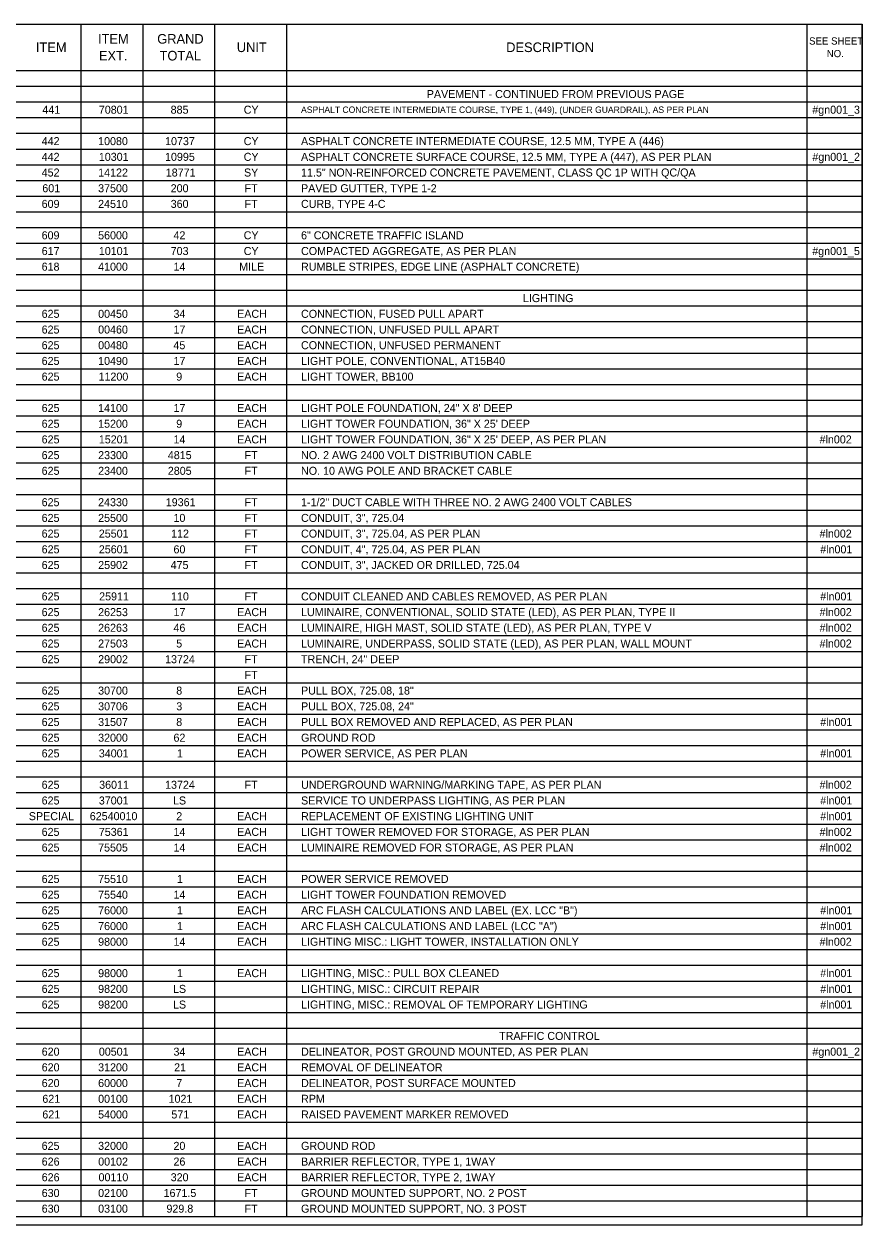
# Model space of a CAD drawing. Extents: x -542 to 295, y -281 to 32.
# Drawn here: x -400.58 to -385.9, y -100.59 to -79.59 of the extents above; entities that cross this region are included whole.
import ezdxf

# ---------------------------------------------------------------- set-up
doc = ezdxf.new("R2010")
doc.units = 0
for name, color, linetype in [('SC_Scratch1', 7, 'Continuous'), ('SH_Data', 7, 'Continuous'), ('SH_Text', 7, 'Continuous')]:
    doc.layers.add(name, color=color, linetype=linetype)

msp = doc.modelspace()

# ---------------------------------------------------------------- linework, layer by layer
at = {"layer": 'SC_Scratch1'}
msp.add_lwpolyline([(-416.421, -79.593), (-385.921, -79.593), (-385.921, -100.593), (-416.421, -100.593)], close=True, dxfattribs=at)
at = {"layer": 'SH_Data'}
for p, q in [((-416.419, -79.593), (-385.919, -79.593)), ((-399.583, -79.593), (-399.583, -100.444)), ((-398.498, -79.593), (-398.498, -100.444)), ((-397.242, -79.593), (-397.242, -100.444)), ((-395.986, -79.593), (-395.986, -100.444)), ((-386.887, -79.593), (-386.887, -100.444)), ((-385.919, -79.593), (-385.919, -100.444)), ((-416.419, -80.405), (-385.919, -80.405)), ((-416.419, -80.68), (-385.919, -80.68)), ((-416.419, -80.954), (-385.919, -80.954)), ((-416.419, -80.954), (-385.919, -80.954)), ((-416.419, -81.229), (-385.919, -81.229)), ((-416.419, -81.503), (-385.919, -81.503)), ((-416.419, -81.778), (-385.919, -81.778)), ((-416.419, -82.052), (-385.919, -82.052)), ((-416.419, -82.327), (-385.919, -82.327)), ((-416.419, -82.601), (-385.919, -82.601)), ((-416.419, -82.876), (-385.919, -82.876)), ((-416.419, -83.15), (-385.919, -83.15)), ((-416.419, -83.425), (-385.919, -83.425)), ((-416.419, -83.699), (-385.919, -83.699)), ((-416.419, -83.974), (-385.919, -83.974)), ((-416.419, -84.248), (-385.919, -84.248)), ((-416.419, -84.523), (-385.919, -84.523)), ((-416.419, -84.797), (-385.919, -84.797)), ((-416.419, -85.072), (-385.919, -85.072)), ((-416.419, -85.346), (-385.919, -85.346)), ((-416.419, -85.621), (-385.919, -85.621)), ((-416.419, -85.895), (-385.919, -85.895)), ((-416.419, -86.17), (-385.919, -86.17)), ((-416.419, -86.444), (-385.919, -86.444)), ((-416.419, -86.719), (-385.919, -86.719)), ((-416.419, -86.993), (-385.919, -86.993)), ((-416.419, -87.268), (-385.919, -87.268)), ((-416.419, -87.542), (-385.919, -87.542)), ((-416.419, -87.817), (-385.919, -87.817)), ((-416.419, -88.091), (-385.919, -88.091)), ((-416.419, -88.366), (-385.919, -88.366)), ((-416.419, -88.64), (-385.919, -88.64)), ((-416.419, -88.915), (-385.919, -88.915)), ((-416.419, -89.189), (-385.919, -89.189)), ((-416.419, -89.464), (-385.919, -89.464)), ((-416.419, -89.738), (-385.919, -89.738)), ((-416.419, -90.013), (-385.919, -90.013)), ((-416.419, -90.287), (-385.919, -90.287)), ((-416.419, -90.562), (-385.919, -90.562)), ((-416.419, -90.836), (-385.919, -90.836)), ((-416.419, -91.111), (-385.919, -91.111)), ((-416.419, -91.385), (-385.919, -91.385)), ((-416.419, -91.66), (-385.919, -91.66)), ((-416.419, -91.935), (-385.919, -91.935)), ((-416.419, -92.209), (-385.919, -92.209)), ((-416.419, -92.484), (-385.919, -92.484)), ((-416.419, -92.758), (-385.919, -92.758)), ((-416.419, -93.033), (-385.919, -93.033)), ((-416.419, -93.307), (-385.919, -93.307)), ((-416.419, -93.582), (-385.919, -93.582)), ((-416.419, -93.856), (-385.919, -93.856)), ((-416.419, -94.131), (-385.919, -94.131)), ((-416.419, -94.405), (-385.919, -94.405)), ((-416.419, -94.68), (-385.919, -94.68)), ((-416.419, -94.954), (-385.919, -94.954)), ((-416.419, -95.229), (-385.919, -95.229)), ((-416.419, -95.503), (-385.919, -95.503)), ((-416.419, -95.778), (-385.919, -95.778)), ((-416.419, -95.778), (-385.919, -95.778)), ((-416.419, -96.052), (-385.919, -96.052)), ((-416.419, -96.327), (-385.919, -96.327)), ((-416.419, -96.601), (-385.919, -96.601)), ((-416.419, -96.876), (-385.919, -96.876)), ((-416.419, -96.876), (-385.919, -96.876)), ((-416.419, -97.15), (-385.919, -97.15)), ((-416.419, -97.425), (-385.919, -97.425)), ((-416.419, -97.699), (-385.919, -97.699)), ((-416.419, -97.974), (-385.919, -97.974)), ((-416.419, -98.248), (-385.919, -98.248)), ((-416.419, -98.523), (-385.919, -98.523)), ((-416.419, -98.797), (-385.919, -98.797)), ((-416.419, -99.072), (-385.919, -99.072)), ((-416.419, -99.346), (-385.919, -99.346)), ((-416.419, -99.621), (-385.919, -99.621)), ((-416.419, -99.895), (-385.919, -99.895)), ((-416.419, -100.17), (-385.919, -100.17)), ((-416.419, -100.444), (-385.919, -100.444)), ((-416.419, -100.444), (-385.919, -100.444))]:
    msp.add_line(p, q, dxfattribs=at)

# ---------------------------------------------------------------- texts
at = {"layer": 'SH_Text'}
for s, height, p in [('ITEM', 0.168, (-399.282, -79.936)), ('GRAND ', 0.168, (-398.246, -79.936)), ('ITEM', 0.168, (-400.368, -80.083)), ('UNIT', 0.168, (-396.855, -80.083)), ('DESCRIPTION', 0.168, (-392.143, -80.083)), ('SEE SHEET ', 0.126, (-386.845, -79.952)), ('EXT.', 0.168, (-399.266, -80.23)), ('TOTAL', 0.168, (-398.205, -80.23)), ('NO.', 0.126, (-386.537, -80.172)), ('PAVEMENT - CONTINUED FROM PREVIOUS PAGE', 0.14, (-393.532, -80.887)), ('441', 0.14, (-400.256, -81.161)), ('70801', 0.14, (-399.268, -81.161)), ('885', 0.14, (-398.012, -81.161)), ('CY', 0.14, (-396.734, -81.161)), ('ASPHALT CONCRETE INTERMEDIATE COURSE, TYPE 1, (449), (UNDER GUARDRAIL), AS PER PLAN', 0.112, (-395.731, -81.147)), ('#gn001_3', 0.14, (-386.789, -81.161)), ('442', 0.14, (-400.267, -81.71)), ('10080', 0.14, (-399.28, -81.71)), ('10737', 0.14, (-398.109, -81.71)), ('CY', 0.14, (-396.734, -81.71)), ('ASPHALT CONCRETE INTERMEDIATE COURSE, 12.5 MM, TYPE A (446)', 0.14, (-395.731, -81.71)), ('442', 0.14, (-400.267, -81.985)), ('10301', 0.14, (-399.268, -81.985)), ('10995', 0.14, (-398.11, -81.985)), ('CY', 0.14, (-396.734, -81.985)), ('ASPHALT CONCRETE SURFACE COURSE, 12.5 MM, TYPE A (447), AS PER PLAN', 0.14, (-395.731, -81.985)), ('#gn001_2', 0.14, (-386.788, -81.985)), ('452', 0.14, (-400.267, -82.259)), ('14122', 0.14, (-399.279, -82.259)), ('18771', 0.14, (-398.097, -82.259)), ('SY', 0.14, (-396.729, -82.259)), ('11.5" NON-REINFORCED CONCRETE PAVEMENT, CLASS QC 1P WITH QC/QA', 0.14, (-395.731, -82.259)), ('601', 0.14, (-400.256, -82.534)), ('37500', 0.14, (-399.28, -82.534)), ('200', 0.14, (-398.011, -82.534)), ('FT', 0.14, (-396.718, -82.534)), ('PAVED GUTTER, TYPE 1-2', 0.14, (-395.731, -82.534)), ('609', 0.14, (-400.268, -82.808)), ('24510', 0.14, (-399.28, -82.808)), ('360', 0.14, (-398.011, -82.808)), ('FT', 0.14, (-396.718, -82.808)), ('CURB, TYPE 4-C', 0.14, (-395.731, -82.808)), ('609', 0.14, (-400.268, -83.357)), ('56000', 0.14, (-399.28, -83.357)), ('42', 0.14, (-397.962, -83.357)), ('CY', 0.14, (-396.734, -83.357)), ('6" CONCRETE TRAFFIC ISLAND', 0.14, (-395.731, -83.357)), ('617', 0.14, (-400.267, -83.632)), ('10101', 0.14, (-399.268, -83.632)), ('703', 0.14, (-398.011, -83.632)), ('CY', 0.14, (-396.734, -83.632)), ('COMPACTED AGGREGATE, AS PER PLAN', 0.14, (-395.731, -83.632)), ('#gn001_5', 0.14, (-386.79, -83.632)), ('618', 0.14, (-400.268, -83.906)), ('41000', 0.14, (-399.28, -83.906)), ('14', 0.14, (-397.962, -83.906)), ('MILE', 0.14, (-396.813, -83.906)), ('RUMBLE STRIPES, EDGE LINE (ASPHALT CONCRETE)', 0.14, (-395.731, -83.906)), ('LIGHTING', 0.14, (-391.85, -84.455)), ('625', 0.14, (-400.268, -84.73)), ('00450', 0.14, (-399.28, -84.73)), ('34', 0.14, (-397.962, -84.73)), ('EACH', 0.14, (-396.849, -84.73)), ('CONNECTION, FUSED PULL APART', 0.14, (-395.731, -84.73)), ('625', 0.14, (-400.268, -85.005)), ('00460', 0.14, (-399.28, -85.005)), ('17', 0.14, (-397.962, -85.005)), ('EACH', 0.14, (-396.849, -85.005)), ('CONNECTION, UNFUSED PULL APART', 0.14, (-395.731, -85.005)), ('625', 0.14, (-400.268, -85.279)), ('00480', 0.14, (-399.28, -85.279)), ('45', 0.14, (-397.963, -85.279)), ('EACH', 0.14, (-396.849, -85.279)), ('CONNECTION, UNFUSED PERMANENT', 0.14, (-395.731, -85.279)), ('625', 0.14, (-400.268, -85.554)), ('10490', 0.14, (-399.28, -85.554)), ('17', 0.14, (-397.962, -85.554)), ('EACH', 0.14, (-396.849, -85.554)), ('LIGHT POLE, CONVENTIONAL, AT15B40', 0.14, (-395.731, -85.554)), ('625', 0.14, (-400.268, -85.828)), ('11200', 0.14, (-399.273, -85.828)), ('9', 0.14, (-397.914, -85.828)), ('EACH', 0.14, (-396.849, -85.828)), ('LIGHT TOWER, BB100', 0.14, (-395.731, -85.828)), ('625', 0.14, (-400.268, -86.377)), ('14100', 0.14, (-399.28, -86.377)), ('17', 0.14, (-397.962, -86.377)), ('EACH', 0.14, (-396.849, -86.377)), ('LIGHT POLE FOUNDATION, 24" X 8\' DEEP', 0.14, (-395.731, -86.377)), ('625', 0.14, (-400.268, -86.652)), ('15200', 0.14, (-399.28, -86.652)), ('9', 0.14, (-397.914, -86.652)), ('EACH', 0.14, (-396.849, -86.652)), ('LIGHT TOWER FOUNDATION, 36" X 25\' DEEP', 0.14, (-395.731, -86.652)), ('625', 0.14, (-400.268, -86.926)), ('15201', 0.14, (-399.268, -86.926)), ('14', 0.14, (-397.962, -86.926)), ('EACH', 0.14, (-396.849, -86.926)), ('LIGHT TOWER FOUNDATION, 36" X 25\' DEEP, AS PER PLAN', 0.14, (-395.731, -86.926)), ('#ln002', 0.14, (-386.662, -86.926)), ('625', 0.14, (-400.268, -87.201)), ('23300', 0.14, (-399.28, -87.201)), ('4815', 0.14, (-398.061, -87.201)), ('FT', 0.14, (-396.718, -87.201)), ('NO. 2 AWG 2400 VOLT DISTRIBUTION CABLE', 0.14, (-395.731, -87.201)), ('625', 0.14, (-400.268, -87.475)), ('23400', 0.14, (-399.28, -87.475)), ('2805', 0.14, (-398.061, -87.475)), ('FT', 0.14, (-396.718, -87.475)), ('NO. 10 AWG POLE AND BRACKET CABLE', 0.14, (-395.731, -87.475)), ('625', 0.14, (-400.268, -88.024)), ('24330', 0.14, (-399.28, -88.024)), ('19361', 0.14, (-398.097, -88.024)), ('FT', 0.14, (-396.718, -88.024)), ('1-1/2" DUCT CABLE WITH THREE NO. 2 AWG 2400 VOLT CABLES', 0.14, (-395.731, -88.024)), ('625', 0.14, (-400.268, -88.299)), ('25500', 0.14, (-399.28, -88.299)), ('10', 0.14, (-397.962, -88.299)), ('FT', 0.14, (-396.718, -88.299)), ('CONDUIT, 3", 725.04', 0.14, (-395.731, -88.299)), ('625', 0.14, (-400.268, -88.573)), ('25501', 0.14, (-399.268, -88.573)), ('112', 0.14, (-398.004, -88.573)), ('FT', 0.14, (-396.718, -88.573)), ('CONDUIT, 3", 725.04, AS PER PLAN', 0.14, (-395.731, -88.573)), ('#ln002', 0.14, (-386.662, -88.573)), ('625', 0.14, (-400.268, -88.848)), ('25601', 0.14, (-399.268, -88.848)), ('60', 0.14, (-397.962, -88.848)), ('FT', 0.14, (-396.718, -88.848)), ('CONDUIT, 4", 725.04, AS PER PLAN', 0.14, (-395.731, -88.848)), ('#ln001', 0.14, (-386.651, -88.848)), ('625', 0.14, (-400.268, -89.122)), ('25902', 0.14, (-399.279, -89.122)), ('475', 0.14, (-398.012, -89.122)), ('FT', 0.14, (-396.718, -89.122)), ('CONDUIT, 3", JACKED OR DRILLED, 725.04', 0.14, (-395.731, -89.122)), ('625', 0.14, (-400.268, -89.671)), ('25911', 0.14, (-399.262, -89.671)), ('110', 0.14, (-398.005, -89.671)), ('FT', 0.14, (-396.718, -89.671)), ('CONDUIT CLEANED AND CABLES REMOVED, AS PER PLAN', 0.14, (-395.731, -89.671)), ('#ln001', 0.14, (-386.651, -89.671)), ('625', 0.14, (-400.268, -89.946)), ('26253', 0.14, (-399.28, -89.946)), ('17', 0.14, (-397.962, -89.946)), ('EACH', 0.14, (-396.849, -89.946)), ('LUMINAIRE, CONVENTIONAL, SOLID STATE (LED), AS PER PLAN, TYPE II', 0.14, (-395.731, -89.946)), ('#ln002', 0.14, (-386.662, -89.946)), ('625', 0.14, (-400.268, -90.22)), ('26263', 0.14, (-399.28, -90.22)), ('46', 0.14, (-397.962, -90.22)), ('EACH', 0.14, (-396.849, -90.22)), ('LUMINAIRE, HIGH MAST, SOLID STATE (LED), AS PER PLAN, TYPE V', 0.14, (-395.731, -90.22)), ('#ln002', 0.14, (-386.662, -90.22)), ('625', 0.14, (-400.268, -90.495)), ('27503', 0.14, (-399.28, -90.495)), ('5', 0.14, (-397.914, -90.495)), ('EACH', 0.14, (-396.849, -90.495)), ('LUMINAIRE, UNDERPASS, SOLID STATE (LED), AS PER PLAN, WALL MOUNT', 0.14, (-395.731, -90.495)), ('#ln002', 0.14, (-386.662, -90.495)), ('625', 0.14, (-400.268, -90.769)), ('29002', 0.14, (-399.279, -90.769)), ('13724', 0.14, (-398.109, -90.769)), ('FT', 0.14, (-396.718, -90.769)), ('TRENCH, 24" DEEP', 0.14, (-395.731, -90.769)), ('FT', 0.14, (-396.718, -91.044)), ('625', 0.14, (-400.268, -91.318)), ('30700', 0.14, (-399.28, -91.318)), ('8', 0.14, (-397.914, -91.318)), ('EACH', 0.14, (-396.849, -91.318)), ('PULL BOX, 725.08, 18"', 0.14, (-395.731, -91.318)), ('625', 0.14, (-400.268, -91.593)), ('30706', 0.14, (-399.28, -91.593)), ('3', 0.14, (-397.913, -91.593)), ('EACH', 0.14, (-396.849, -91.593)), ('PULL BOX, 725.08, 24"', 0.14, (-395.731, -91.593)), ('625', 0.14, (-400.268, -91.867)), ('31507', 0.14, (-399.28, -91.867)), ('8', 0.14, (-397.914, -91.867)), ('EACH', 0.14, (-396.849, -91.867)), ('PULL BOX REMOVED AND REPLACED, AS PER PLAN', 0.14, (-395.731, -91.867)), ('#ln001', 0.14, (-386.651, -91.867)), ('625', 0.14, (-400.268, -92.142)), ('32000', 0.14, (-399.28, -92.142)), ('62', 0.14, (-397.962, -92.142)), ('EACH', 0.14, (-396.849, -92.142)), ('GROUND ROD', 0.14, (-395.731, -92.142)), ('625', 0.14, (-400.268, -92.416)), ('34001', 0.14, (-399.268, -92.416)), ('1', 0.14, (-397.902, -92.416)), ('EACH', 0.14, (-396.849, -92.416)), ('POWER SERVICE, AS PER PLAN', 0.14, (-395.731, -92.416)), ('#ln001', 0.14, (-386.651, -92.416)), ('UNDERGROUND WARNING/MARKING TAPE, AS PER PLAN', 0.14, (-395.731, -92.965)), ('#ln002', 0.14, (-386.662, -92.965)), ('625', 0.14, (-400.268, -92.965)), ('36011', 0.14, (-399.262, -92.965)), ('13724', 0.14, (-398.109, -92.965)), ('FT', 0.14, (-396.718, -92.965)), ('625', 0.14, (-400.268, -93.24)), ('37001', 0.14, (-399.268, -93.24)), ('LS', 0.14, (-397.971, -93.24)), ('SERVICE TO UNDERPASS LIGHTING, AS PER PLAN', 0.14, (-395.731, -93.24)), ('#ln001', 0.14, (-386.651, -93.24)), ('SPECIAL', 0.14, (-400.492, -93.514)), ('62540010', 0.14, (-399.426, -93.514)), ('2', 0.14, (-397.913, -93.514)), ('EACH', 0.14, (-396.849, -93.514)), ('REPLACEMENT OF EXISTING LIGHTING UNIT', 0.14, (-395.731, -93.514)), ('#ln001', 0.14, (-386.651, -93.514)), ('625', 0.14, (-400.268, -93.789)), ('75361', 0.14, (-399.268, -93.789)), ('14', 0.14, (-397.962, -93.789)), ('EACH', 0.14, (-396.849, -93.789)), ('LIGHT TOWER REMOVED FOR STORAGE, AS PER PLAN', 0.14, (-395.731, -93.789)), ('#ln002', 0.14, (-386.662, -93.789)), ('625', 0.14, (-400.268, -94.063)), ('75505', 0.14, (-399.28, -94.063)), ('14', 0.14, (-397.962, -94.063)), ('EACH', 0.14, (-396.849, -94.063)), ('LUMINAIRE REMOVED FOR STORAGE, AS PER PLAN', 0.14, (-395.731, -94.063)), ('#ln002', 0.14, (-386.662, -94.063)), ('625', 0.14, (-400.268, -94.612)), ('75510', 0.14, (-399.28, -94.612)), ('1', 0.14, (-397.902, -94.612)), ('EACH', 0.14, (-396.849, -94.612)), ('POWER SERVICE REMOVED', 0.14, (-395.731, -94.612)), ('625', 0.14, (-400.268, -94.887)), ('75540', 0.14, (-399.28, -94.887)), ('14', 0.14, (-397.962, -94.887)), ('EACH', 0.14, (-396.849, -94.887)), ('LIGHT TOWER FOUNDATION REMOVED', 0.14, (-395.731, -94.887)), ('625', 0.14, (-400.268, -95.161)), ('76000', 0.14, (-399.28, -95.161)), ('1', 0.14, (-397.902, -95.161)), ('EACH', 0.14, (-396.849, -95.161)), ('ARC FLASH CALCULATIONS AND LABEL (EX. LCC "B")', 0.14, (-395.731, -95.161)), ('#ln001', 0.14, (-386.651, -95.161)), ('625', 0.14, (-400.268, -95.436)), ('76000', 0.14, (-399.28, -95.436)), ('1', 0.14, (-397.902, -95.436)), ('EACH', 0.14, (-396.849, -95.436)), ('ARC FLASH CALCULATIONS AND LABEL (LCC "A")', 0.14, (-395.731, -95.436)), ('#ln001', 0.14, (-386.651, -95.436)), ('625', 0.14, (-400.268, -95.71)), ('98000', 0.14, (-399.28, -95.71)), ('14', 0.14, (-397.962, -95.71)), ('EACH', 0.14, (-396.849, -95.71)), ('LIGHTING MISC.: LIGHT TOWER, INSTALLATION ONLY', 0.14, (-395.731, -95.71)), ('#ln002', 0.14, (-386.662, -95.71)), ('625', 0.14, (-400.268, -96.259)), ('98000', 0.14, (-399.28, -96.259)), ('1', 0.14, (-397.902, -96.259)), ('EACH', 0.14, (-396.849, -96.259)), ('LIGHTING, MISC.: PULL BOX CLEANED', 0.14, (-395.731, -96.259)), ('#ln001', 0.14, (-386.651, -96.259)), ('#ln001', 0.14, (-386.651, -96.534)), ('625', 0.14, (-400.268, -96.534)), ('98200', 0.14, (-399.28, -96.534)), ('LS', 0.14, (-397.971, -96.534)), ('LIGHTING, MISC.: CIRCUIT REPAIR', 0.14, (-395.731, -96.534)), ('625', 0.14, (-400.268, -96.808)), ('98200', 0.14, (-399.28, -96.808)), ('LS', 0.14, (-397.971, -96.808)), ('LIGHTING, MISC.: REMOVAL OF TEMPORARY LIGHTING', 0.14, (-395.731, -96.808)), ('#ln001', 0.14, (-386.651, -96.808)), ('TRAFFIC CONTROL', 0.14, (-392.266, -97.357)), ('620', 0.14, (-400.267, -97.632)), ('00501', 0.14, (-399.268, -97.632)), ('34', 0.14, (-397.962, -97.632)), ('EACH', 0.14, (-396.849, -97.632)), ('DELINEATOR, POST GROUND MOUNTED, AS PER PLAN', 0.14, (-395.731, -97.632)), ('#gn001_2', 0.14, (-386.788, -97.632)), ('620', 0.14, (-400.267, -97.906)), ('31200', 0.14, (-399.28, -97.906)), ('21', 0.14, (-397.951, -97.906)), ('EACH', 0.14, (-396.849, -97.906)), ('REMOVAL OF DELINEATOR', 0.14, (-395.731, -97.906)), ('620', 0.14, (-400.267, -98.181)), ('60000', 0.14, (-399.28, -98.181)), ('7', 0.14, (-397.913, -98.181)), ('EACH', 0.14, (-396.849, -98.181)), ('DELINEATOR, POST SURFACE MOUNTED', 0.14, (-395.731, -98.181)), ('621', 0.14, (-400.256, -98.456)), ('00100', 0.14, (-399.28, -98.456)), ('1021', 0.14, (-398.048, -98.456)), ('EACH', 0.14, (-396.849, -98.456)), ('RPM', 0.14, (-395.731, -98.456)), ('621', 0.14, (-400.256, -98.73)), ('54000', 0.14, (-399.28, -98.73)), ('571', 0.14, (-397.999, -98.73)), ('EACH', 0.14, (-396.849, -98.73)), ('RAISED PAVEMENT MARKER REMOVED', 0.14, (-395.731, -98.73)), ('625', 0.14, (-400.268, -99.279)), ('32000', 0.14, (-399.28, -99.279)), ('20', 0.14, (-397.962, -99.279)), ('EACH', 0.14, (-396.849, -99.279)), ('GROUND ROD', 0.14, (-395.731, -99.279)), ('626', 0.14, (-400.267, -99.554)), ('00102', 0.14, (-399.279, -99.554)), ('26', 0.14, (-397.962, -99.554)), ('EACH', 0.14, (-396.849, -99.554)), ('BARRIER REFLECTOR, TYPE 1, 1WAY', 0.14, (-395.731, -99.554)), ('626', 0.14, (-400.267, -99.828)), ('00110', 0.14, (-399.273, -99.828)), ('320', 0.14, (-398.011, -99.828)), ('EACH', 0.14, (-396.849, -99.828)), ('BARRIER REFLECTOR, TYPE 2, 1WAY', 0.14, (-395.731, -99.828)), ('630', 0.14, (-400.267, -100.103)), ('02100', 0.14, (-399.28, -100.103)), ('1671.5', 0.14, (-398.135, -100.103)), ('FT', 0.14, (-396.718, -100.103)), ('GROUND MOUNTED SUPPORT, NO. 2 POST', 0.14, (-395.731, -100.103)), ('630', 0.14, (-400.267, -100.377)), ('03100', 0.14, (-399.28, -100.377)), ('929.8', 0.14, (-398.085, -100.377)), ('FT', 0.14, (-396.718, -100.377)), ('GROUND MOUNTED SUPPORT, NO. 3 POST', 0.14, (-395.731, -100.377))]:
    msp.add_text(s, height=height, dxfattribs=at).set_placement(p)

doc.saveas('drawing.dxf')
